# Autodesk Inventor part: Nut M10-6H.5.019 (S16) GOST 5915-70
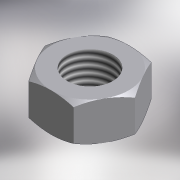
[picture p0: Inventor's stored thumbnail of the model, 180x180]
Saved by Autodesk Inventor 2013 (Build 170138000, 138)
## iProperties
Shininess: 0.0
Length Units: 11269
Angle Units: 11279
Time Units: 11290
Mass Units: 11283
Length Display Precision: 3
Angle Display Precision: 2
Created: 2001-04
Part Number: Nut M10-6H.5.019 (S16) GOST 5915-70
Material: Steel, Mild
Description: Nut M10-6H.5.019 (S16) GOST 5915-70
Document SubType Name: Modeling
Designer: =<Author>
Mass: 11.2552 g
Surface Area: 10.7859 cm^2
Volume: 1.43196 cm^3
Density: 7.86 g/cm^3
Density: 0.0
Volumn: 0.0
Area: 0.0
PropertySet Name: Model Information
Control State: 0
Master: False
Checked Out: True
Checked Out Date: 2008-10-15
Last Check In Date: 2008-10-15
Author: tevgeniy
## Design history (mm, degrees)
node "ExtrusionBlind1" dims "d6" = 8.4, "d7" = 0
  sketch "Sketch1"
    geometry: L1 (484.39, 469.325)-(474.575, 469.325); L2 (489.297, 460.825)-(484.39, 469.325); L3 (484.39, 452.325)-(489.297, 460.825); L4 (474.575, 452.325)-(484.39, 452.325); L5 (469.667, 460.825)-(474.575, 452.325); L6 (474.575, 469.325)-(469.667, 460.825); C1 r 8.5 at (479.482, 460.825)
    constraints: 12 end point, 6 tangent, 3 parallel, 1 centre point, 1 horizontal, 1 other
    dimensions: "d1" = 120 deg angle of L1 L2; "d3" = 120 deg angle of L5 L6; "d5" = 17 diameter of C1; "d27" = 17 distance between parallel lines of L4 L1 (derived)
node "ExtrusionThru1" dims "d14" = 0.13, "d15" = 0
  sketch "Sketch2"
    geometry: L1 (-472.982, -455.084)-(-472.482, -455.95); L2 (-479.377, -452.325)-(-478.377, -452.325); L3 (-489.203, -460.662)-(-488.703, -459.796); C1 r 5 at (-479.482, -460.825); C2 r 8.5 at (-479.482, -460.825)
    constraints: 6 end point, 3 tangent, 2 centre point, 1 coincident
    dimensions: "d13" = 10 diameter of C1
node "WorkAxis1"
node "WorkPlane1"
node "RevolutionAngle1" dims "d24" = 360 deg
  sketch "Sketch3"
    geometry: L1 (0, 0)-(0, 8.4); L2 (8.5, 0)-(0, 0); L3 (9.815, 0.759)-(8.5, 0); L4 (9.815, 7.641)-(9.815, 0.759); L5 (8.5, 8.4)-(9.815, 7.641); L6 (0, 8.4)-(8.5, 8.4); L7 (0, 8.4)-(-1, 8.4); L8 (-0.105, 0)-(-1.105, 0); L9 (9.815, 8.4)-(9.815, 7.4); L10 (0, 17.846)-(0, -9.446); L11 (0, 17.846)-(0, -9.446)
    constraints: 22 end point, 4 collinear, 2 horizontal, 2 vertical
    dimensions: "d17" = 8.5 distance of L1.end L5.start; "d19" = 30 deg angle of L6 L5; "d21" = 30 deg angle of L3 L2; "d23" = 0 horizontal distance of L5.start L2.start
thread "Thread1" dims "d25" = 10, "d26" = 0
body "Solid1"
other parameters: "d0" = 120 deg (derived), "d2" = 120 deg (derived), "d4" = 17 (derived), "d8" = 0, "d9" = 0, "d10" = 0, "d11" = 0, "d16" = 8.5 (derived), "d18" = 30 deg (derived), "d20" = 30 deg (derived), "d22" = 0 (derived), "d28" = 0
